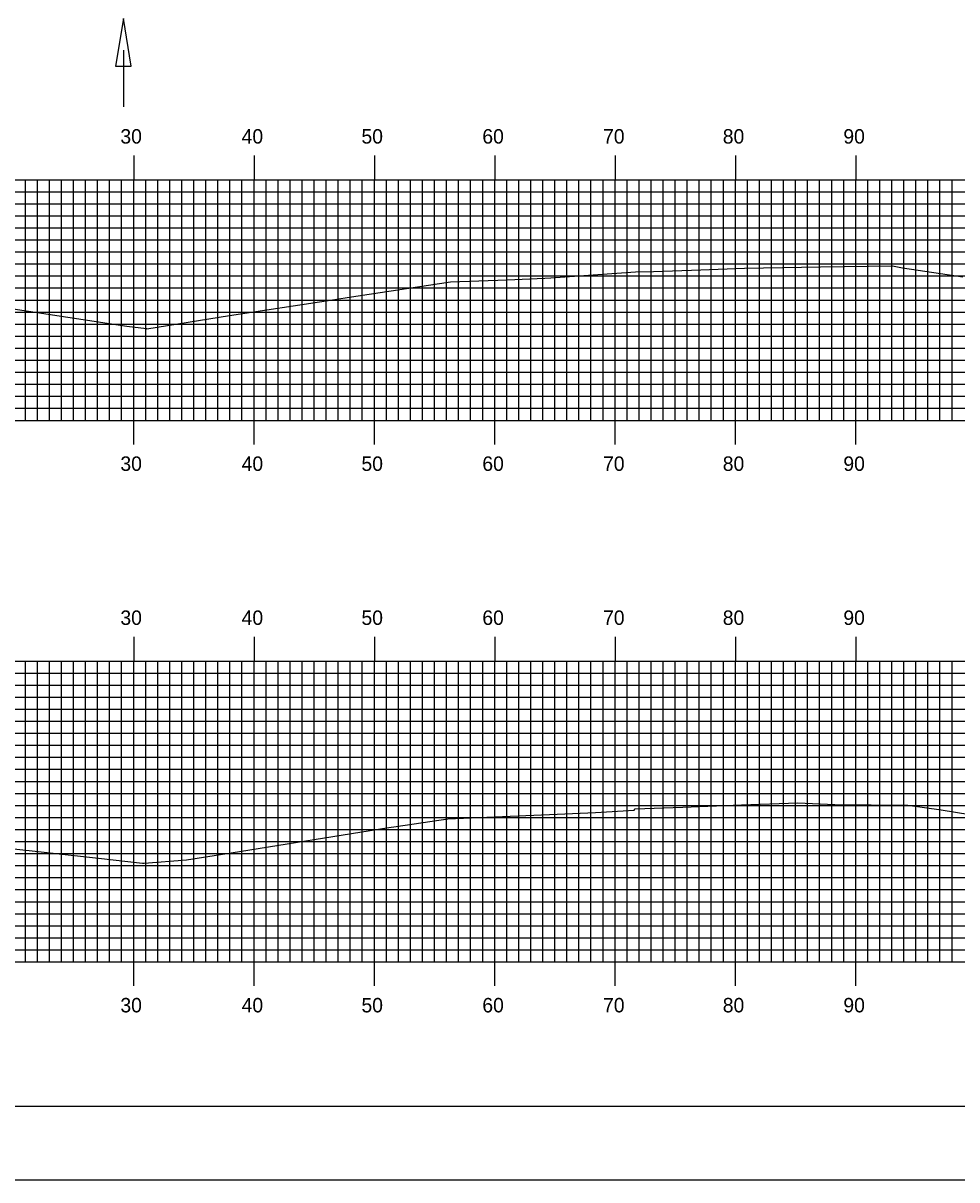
# Model space of a CAD drawing. Extents: x 850746 to 851089, y 366605 to 366825.
# Drawn here: x 850932.2 to 851009.8, y 366604.9 to 366701.1 of the extents above; entities that cross this region are included whole.
import ezdxf

# ---------------------------------------------------------------- set-up
doc = ezdxf.new("R2010")
doc.units = 0
for name, color, linetype in [('BORDER', 7, 'Continuous'), ('D_Drainage_Ditch_Line', 7, 'Continuous'), ('H_V ANNOTATION', 7, 'Continuous'), ('M_Roadway_Centerline', 7, 'Continuous'), ('MAJOR', 7, 'Continuous'), ('MINOR', 7, 'Continuous'), ('PLOT BOUNDARY', 7, 'Continuous'), ('S_Roadway_Centerline', 7, 'Continuous')]:
    doc.layers.add(name, color=color, linetype=linetype)

msp = doc.modelspace()

# ---------------------------------------------------------------- linework, layer by layer
at = {"layer": 'BORDER'}
msp.add_lwpolyline([(850761.825, 366611.055), (851081.825, 366611.055), (851081.825, 366821.055), (850761.825, 366821.055)], close=True, dxfattribs=at)
at = {"layer": 'D_Drainage_Ditch_Line'}
msp.add_line((850940.572, 366698.812), (850940.572, 366694.113), dxfattribs=at)
msp.add_lwpolyline([(850939.916, 366697.499), (850941.228, 366697.499), (850940.572, 366701.436)], close=True, dxfattribs=at)
at = {"layer": 'MAJOR'}
for p, q in [((850941.425, 366690.059), (850941.425, 366688.055)), ((850951.425, 366690.059), (850951.425, 366688.055)), ((850961.425, 366690.059), (850961.425, 366688.055)), ((850971.425, 366690.059), (850971.425, 366688.055)), ((850981.425, 366690.059), (850981.425, 366688.055)), ((850991.425, 366690.059), (850991.425, 366688.055)), ((851001.425, 366690.059), (851001.425, 366688.055)), ((850771.425, 366688.055), (851051.425, 366688.055)), ((850771.425, 366688.055), (851051.425, 366688.055)), ((850941.425, 366668.055), (850941.425, 366688.055)), ((850951.425, 366668.055), (850951.425, 366688.055)), ((850961.425, 366668.055), (850961.425, 366688.055)), ((850971.425, 366668.055), (850971.425, 366688.055)), ((850981.425, 366668.055), (850981.425, 366688.055)), ((850991.425, 366668.055), (850991.425, 366688.055)), ((851001.425, 366668.055), (851001.425, 366688.055)), ((850771.425, 366683.055), (851051.425, 366683.055)), ((850771.425, 366678.055), (851051.425, 366678.055)), ((850771.425, 366673.055), (851051.425, 366673.055)), ((850771.425, 366668.055), (851051.425, 366668.055)), ((850771.425, 366668.055), (851051.425, 366668.055)), ((850941.425, 366666.051), (850941.425, 366668.055)), ((850951.425, 366666.051), (850951.425, 366668.055)), ((850961.425, 366666.051), (850961.425, 366668.055)), ((850971.425, 366666.051), (850971.425, 366668.055)), ((850981.425, 366666.051), (850981.425, 366668.055)), ((850991.425, 366666.051), (850991.425, 366668.055)), ((851001.425, 366666.051), (851001.425, 366668.055)), ((850941.425, 366650.059), (850941.425, 366648.055)), ((850951.425, 366650.059), (850951.425, 366648.055)), ((850961.425, 366650.059), (850961.425, 366648.055)), ((850971.425, 366650.059), (850971.425, 366648.055)), ((850981.425, 366650.059), (850981.425, 366648.055)), ((850991.425, 366650.059), (850991.425, 366648.055)), ((851001.425, 366650.059), (851001.425, 366648.055)), ((850771.425, 366648.055), (851051.425, 366648.055)), ((850771.425, 366648.055), (851051.425, 366648.055)), ((850941.425, 366623.055), (850941.425, 366648.055)), ((850951.425, 366623.055), (850951.425, 366648.055)), ((850961.425, 366623.055), (850961.425, 366648.055)), ((850971.425, 366623.055), (850971.425, 366648.055)), ((850981.425, 366623.055), (850981.425, 366648.055)), ((850991.425, 366623.055), (850991.425, 366648.055)), ((851001.425, 366623.055), (851001.425, 366648.055)), ((850771.425, 366643.055), (851051.425, 366643.055)), ((850771.425, 366638.055), (851051.425, 366638.055)), ((850771.425, 366633.055), (851051.425, 366633.055)), ((850771.425, 366628.055), (851051.425, 366628.055)), ((850771.425, 366623.055), (851051.425, 366623.055)), ((850771.425, 366623.055), (851051.425, 366623.055)), ((850941.425, 366621.051), (850941.425, 366623.055)), ((850951.425, 366621.051), (850951.425, 366623.055)), ((850961.425, 366621.051), (850961.425, 366623.055)), ((850971.425, 366621.051), (850971.425, 366623.055)), ((850981.425, 366621.051), (850981.425, 366623.055)), ((850991.425, 366621.051), (850991.425, 366623.055)), ((851001.425, 366621.051), (851001.425, 366623.055))]:
    msp.add_line(p, q, dxfattribs=at)
at = {"layer": 'MINOR'}
for p, q in [((850932.425, 366668.055), (850932.425, 366688.055)), ((850933.425, 366668.055), (850933.425, 366688.055)), ((850934.425, 366668.055), (850934.425, 366688.055)), ((850935.425, 366668.055), (850935.425, 366688.055)), ((850936.425, 366668.055), (850936.425, 366688.055)), ((850937.425, 366668.055), (850937.425, 366688.055)), ((850938.425, 366668.055), (850938.425, 366688.055)), ((850939.425, 366668.055), (850939.425, 366688.055)), ((850940.425, 366668.055), (850940.425, 366688.055)), ((850942.425, 366668.055), (850942.425, 366688.055)), ((850943.425, 366668.055), (850943.425, 366688.055)), ((850944.425, 366668.055), (850944.425, 366688.055)), ((850945.425, 366668.055), (850945.425, 366688.055)), ((850946.425, 366668.055), (850946.425, 366688.055)), ((850947.425, 366668.055), (850947.425, 366688.055)), ((850948.425, 366668.055), (850948.425, 366688.055)), ((850949.425, 366668.055), (850949.425, 366688.055)), ((850950.425, 366668.055), (850950.425, 366688.055)), ((850952.425, 366668.055), (850952.425, 366688.055)), ((850953.425, 366668.055), (850953.425, 366688.055)), ((850954.425, 366668.055), (850954.425, 366688.055)), ((850955.425, 366668.055), (850955.425, 366688.055)), ((850956.425, 366668.055), (850956.425, 366688.055)), ((850957.425, 366668.055), (850957.425, 366688.055)), ((850958.425, 366668.055), (850958.425, 366688.055)), ((850959.425, 366668.055), (850959.425, 366688.055)), ((850960.425, 366668.055), (850960.425, 366688.055)), ((850962.425, 366668.055), (850962.425, 366688.055)), ((850963.425, 366668.055), (850963.425, 366688.055)), ((850964.425, 366668.055), (850964.425, 366688.055)), ((850965.425, 366668.055), (850965.425, 366688.055)), ((850966.425, 366668.055), (850966.425, 366688.055)), ((850967.425, 366668.055), (850967.425, 366688.055)), ((850968.425, 366668.055), (850968.425, 366688.055)), ((850969.425, 366668.055), (850969.425, 366688.055)), ((850970.425, 366668.055), (850970.425, 366688.055)), ((850972.425, 366668.055), (850972.425, 366688.055)), ((850973.425, 366668.055), (850973.425, 366688.055)), ((850974.425, 366668.055), (850974.425, 366688.055)), ((850975.425, 366668.055), (850975.425, 366688.055)), ((850976.425, 366668.055), (850976.425, 366688.055)), ((850977.425, 366668.055), (850977.425, 366688.055)), ((850978.425, 366668.055), (850978.425, 366688.055)), ((850979.425, 366668.055), (850979.425, 366688.055)), ((850980.425, 366668.055), (850980.425, 366688.055)), ((850982.425, 366668.055), (850982.425, 366688.055)), ((850983.425, 366668.055), (850983.425, 366688.055)), ((850984.425, 366668.055), (850984.425, 366688.055)), ((850985.425, 366668.055), (850985.425, 366688.055)), ((850986.425, 366668.055), (850986.425, 366688.055)), ((850987.425, 366668.055), (850987.425, 366688.055)), ((850988.425, 366668.055), (850988.425, 366688.055)), ((850989.425, 366668.055), (850989.425, 366688.055)), ((850990.425, 366668.055), (850990.425, 366688.055)), ((850992.425, 366668.055), (850992.425, 366688.055)), ((850993.425, 366668.055), (850993.425, 366688.055)), ((850994.425, 366668.055), (850994.425, 366688.055)), ((850995.425, 366668.055), (850995.425, 366688.055)), ((850996.425, 366668.055), (850996.425, 366688.055)), ((850997.425, 366668.055), (850997.425, 366688.055)), ((850998.425, 366668.055), (850998.425, 366688.055)), ((850999.425, 366668.055), (850999.425, 366688.055)), ((851000.425, 366668.055), (851000.425, 366688.055)), ((851002.425, 366668.055), (851002.425, 366688.055)), ((851003.425, 366668.055), (851003.425, 366688.055)), ((851004.425, 366668.055), (851004.425, 366688.055)), ((851005.425, 366668.055), (851005.425, 366688.055)), ((851006.425, 366668.055), (851006.425, 366688.055)), ((851007.425, 366668.055), (851007.425, 366688.055)), ((851008.425, 366668.055), (851008.425, 366688.055)), ((851009.425, 366668.055), (851009.425, 366688.055)), ((850771.425, 366687.055), (851051.425, 366687.055)), ((850771.425, 366686.055), (851051.425, 366686.055)), ((850771.425, 366685.055), (851051.425, 366685.055)), ((850771.425, 366684.055), (851051.425, 366684.055)), ((850771.425, 366682.055), (851051.425, 366682.055)), ((850771.425, 366681.055), (851051.425, 366681.055)), ((850771.425, 366680.055), (851051.425, 366680.055)), ((850771.425, 366679.055), (851051.425, 366679.055)), ((850771.425, 366677.055), (851051.425, 366677.055)), ((850771.425, 366676.055), (851051.425, 366676.055)), ((850771.425, 366675.055), (851051.425, 366675.055)), ((850771.425, 366674.055), (851051.425, 366674.055)), ((850771.425, 366672.055), (851051.425, 366672.055)), ((850771.425, 366671.055), (851051.425, 366671.055)), ((850771.425, 366670.055), (851051.425, 366670.055)), ((850771.425, 366669.055), (851051.425, 366669.055)), ((850932.425, 366623.055), (850932.425, 366648.055)), ((850933.425, 366623.055), (850933.425, 366648.055)), ((850934.425, 366623.055), (850934.425, 366648.055)), ((850935.425, 366623.055), (850935.425, 366648.055)), ((850936.425, 366623.055), (850936.425, 366648.055)), ((850937.425, 366623.055), (850937.425, 366648.055)), ((850938.425, 366623.055), (850938.425, 366648.055)), ((850939.425, 366623.055), (850939.425, 366648.055)), ((850940.425, 366623.055), (850940.425, 366648.055)), ((850942.425, 366623.055), (850942.425, 366648.055)), ((850943.425, 366623.055), (850943.425, 366648.055)), ((850944.425, 366623.055), (850944.425, 366648.055)), ((850945.425, 366623.055), (850945.425, 366648.055)), ((850946.425, 366623.055), (850946.425, 366648.055)), ((850947.425, 366623.055), (850947.425, 366648.055)), ((850948.425, 366623.055), (850948.425, 366648.055)), ((850949.425, 366623.055), (850949.425, 366648.055)), ((850950.425, 366623.055), (850950.425, 366648.055)), ((850952.425, 366623.055), (850952.425, 366648.055)), ((850953.425, 366623.055), (850953.425, 366648.055)), ((850954.425, 366623.055), (850954.425, 366648.055)), ((850955.425, 366623.055), (850955.425, 366648.055)), ((850956.425, 366623.055), (850956.425, 366648.055)), ((850957.425, 366623.055), (850957.425, 366648.055)), ((850958.425, 366623.055), (850958.425, 366648.055)), ((850959.425, 366623.055), (850959.425, 366648.055)), ((850960.425, 366623.055), (850960.425, 366648.055)), ((850962.425, 366623.055), (850962.425, 366648.055)), ((850963.425, 366623.055), (850963.425, 366648.055)), ((850964.425, 366623.055), (850964.425, 366648.055)), ((850965.425, 366623.055), (850965.425, 366648.055)), ((850966.425, 366623.055), (850966.425, 366648.055)), ((850967.425, 366623.055), (850967.425, 366648.055)), ((850968.425, 366623.055), (850968.425, 366648.055)), ((850969.425, 366623.055), (850969.425, 366648.055)), ((850970.425, 366623.055), (850970.425, 366648.055)), ((850972.425, 366623.055), (850972.425, 366648.055)), ((850973.425, 366623.055), (850973.425, 366648.055)), ((850974.425, 366623.055), (850974.425, 366648.055)), ((850975.425, 366623.055), (850975.425, 366648.055)), ((850976.425, 366623.055), (850976.425, 366648.055)), ((850977.425, 366623.055), (850977.425, 366648.055)), ((850978.425, 366623.055), (850978.425, 366648.055)), ((850979.425, 366623.055), (850979.425, 366648.055)), ((850980.425, 366623.055), (850980.425, 366648.055)), ((850982.425, 366623.055), (850982.425, 366648.055)), ((850983.425, 366623.055), (850983.425, 366648.055)), ((850984.425, 366623.055), (850984.425, 366648.055)), ((850985.425, 366623.055), (850985.425, 366648.055)), ((850986.425, 366623.055), (850986.425, 366648.055)), ((850987.425, 366623.055), (850987.425, 366648.055)), ((850988.425, 366623.055), (850988.425, 366648.055)), ((850989.425, 366623.055), (850989.425, 366648.055)), ((850990.425, 366623.055), (850990.425, 366648.055)), ((850992.425, 366623.055), (850992.425, 366648.055)), ((850993.425, 366623.055), (850993.425, 366648.055)), ((850994.425, 366623.055), (850994.425, 366648.055)), ((850995.425, 366623.055), (850995.425, 366648.055)), ((850996.425, 366623.055), (850996.425, 366648.055)), ((850997.425, 366623.055), (850997.425, 366648.055)), ((850998.425, 366623.055), (850998.425, 366648.055)), ((850999.425, 366623.055), (850999.425, 366648.055)), ((851000.425, 366623.055), (851000.425, 366648.055)), ((851002.425, 366623.055), (851002.425, 366648.055)), ((851003.425, 366623.055), (851003.425, 366648.055)), ((851004.425, 366623.055), (851004.425, 366648.055)), ((851005.425, 366623.055), (851005.425, 366648.055)), ((851006.425, 366623.055), (851006.425, 366648.055)), ((851007.425, 366623.055), (851007.425, 366648.055)), ((851008.425, 366623.055), (851008.425, 366648.055)), ((851009.425, 366623.055), (851009.425, 366648.055)), ((850771.425, 366647.055), (851051.425, 366647.055)), ((850771.425, 366646.055), (851051.425, 366646.055)), ((850771.425, 366645.055), (851051.425, 366645.055)), ((850771.425, 366644.055), (851051.425, 366644.055)), ((850771.425, 366642.055), (851051.425, 366642.055)), ((850771.425, 366641.055), (851051.425, 366641.055)), ((850771.425, 366640.055), (851051.425, 366640.055)), ((850771.425, 366639.055), (851051.425, 366639.055)), ((850771.425, 366637.055), (851051.425, 366637.055)), ((850771.425, 366636.055), (851051.425, 366636.055)), ((850771.425, 366635.055), (851051.425, 366635.055)), ((850771.425, 366634.055), (851051.425, 366634.055)), ((850771.425, 366632.055), (851051.425, 366632.055)), ((850771.425, 366631.055), (851051.425, 366631.055)), ((850771.425, 366630.055), (851051.425, 366630.055)), ((850771.425, 366629.055), (851051.425, 366629.055)), ((850771.425, 366627.055), (851051.425, 366627.055)), ((850771.425, 366626.055), (851051.425, 366626.055)), ((850771.425, 366625.055), (851051.425, 366625.055)), ((850771.425, 366624.055), (851051.425, 366624.055))]:
    msp.add_line(p, q, dxfattribs=at)
at = {"layer": 'PLOT BOUNDARY'}
msp.add_lwpolyline([(850745.639, 366604.937), (851085.639, 366604.937), (851085.639, 366824.937), (850745.639, 366824.937)], close=True, dxfattribs=at)
at = {"layer": 'S_Roadway_Centerline'}
for points in [[(850926.126, 366678.137), (850940.861, 366675.883), (850942.479, 366675.685), (850942.531, 366675.662), (850949.387, 366676.755), (850957.774, 366678.053), (850959.161, 366678.273), (850967.764, 366679.555), (850972.459, 366679.737), (850975.604, 366679.863), (850976.092, 366679.907), (850983.133, 366680.396), (850984.629, 366680.416), (850988.564, 366680.57), (850992.186, 366680.711), (850998.493, 366680.803), (851004.484, 366680.901), (851005.313, 366680.726), (851010.319, 366679.99)], [(850930.466, 366632.554), (850938.503, 366631.665), (850942.146, 366631.261), (850942.286, 366631.248), (850945.819, 366631.531), (850949.519, 366632.102), (850962.635, 366634.212), (850963.24, 366634.297), (850967.529, 366634.939), (850976.606, 366635.327), (850979.806, 366635.47), (850983.001, 366635.667), (850983.11, 366635.778), (850987.052, 366635.914), (850991.926, 366636.101), (850996.608, 366636.259), (850999.681, 366636.143), (851005.765, 366636.073), (851008.526, 366635.694), (851028.424, 366632.438)]]:
    msp.add_lwpolyline(points, dxfattribs=at)

# ---------------------------------------------------------------- texts
at = {"layer": 'H_V ANNOTATION'}
for s, p in [('30', (850940.323, 366691.055)), ('40', (850950.398, 366691.055)), ('50', (850960.355, 366691.055)), ('60', (850970.398, 366691.055)), ('70', (850980.43, 366691.055)), ('80', (850990.376, 366691.055)), ('90', (851000.398, 366691.055)), ('30', (850940.323, 366663.855)), ('40', (850950.398, 366663.855)), ('50', (850960.355, 366663.855)), ('60', (850970.398, 366663.855)), ('70', (850980.43, 366663.855)), ('80', (850990.376, 366663.855)), ('90', (851000.398, 366663.855)), ('30', (850940.323, 366651.055)), ('40', (850950.398, 366651.055)), ('50', (850960.355, 366651.055)), ('60', (850970.398, 366651.055)), ('70', (850980.43, 366651.055)), ('80', (850990.376, 366651.055)), ('90', (851000.398, 366651.055)), ('30', (850940.323, 366618.855)), ('40', (850950.398, 366618.855)), ('50', (850960.355, 366618.855)), ('60', (850970.398, 366618.855)), ('70', (850980.43, 366618.855)), ('80', (850990.376, 366618.855)), ('90', (851000.398, 366618.855))]:
    msp.add_text(s, height=1.2, dxfattribs=at).set_placement(p)
at = {"layer": 'M_Roadway_Centerline'}
for s, p in [('C', (850983.128, 366680.396)), ('L', (850983.133, 366680.389)), ('C', (850983.105, 366635.778)), ('L', (850983.11, 366635.771))]:
    msp.add_text(s, height=0.0146, dxfattribs=at).set_placement(p)

doc.saveas('drawing.dxf')
